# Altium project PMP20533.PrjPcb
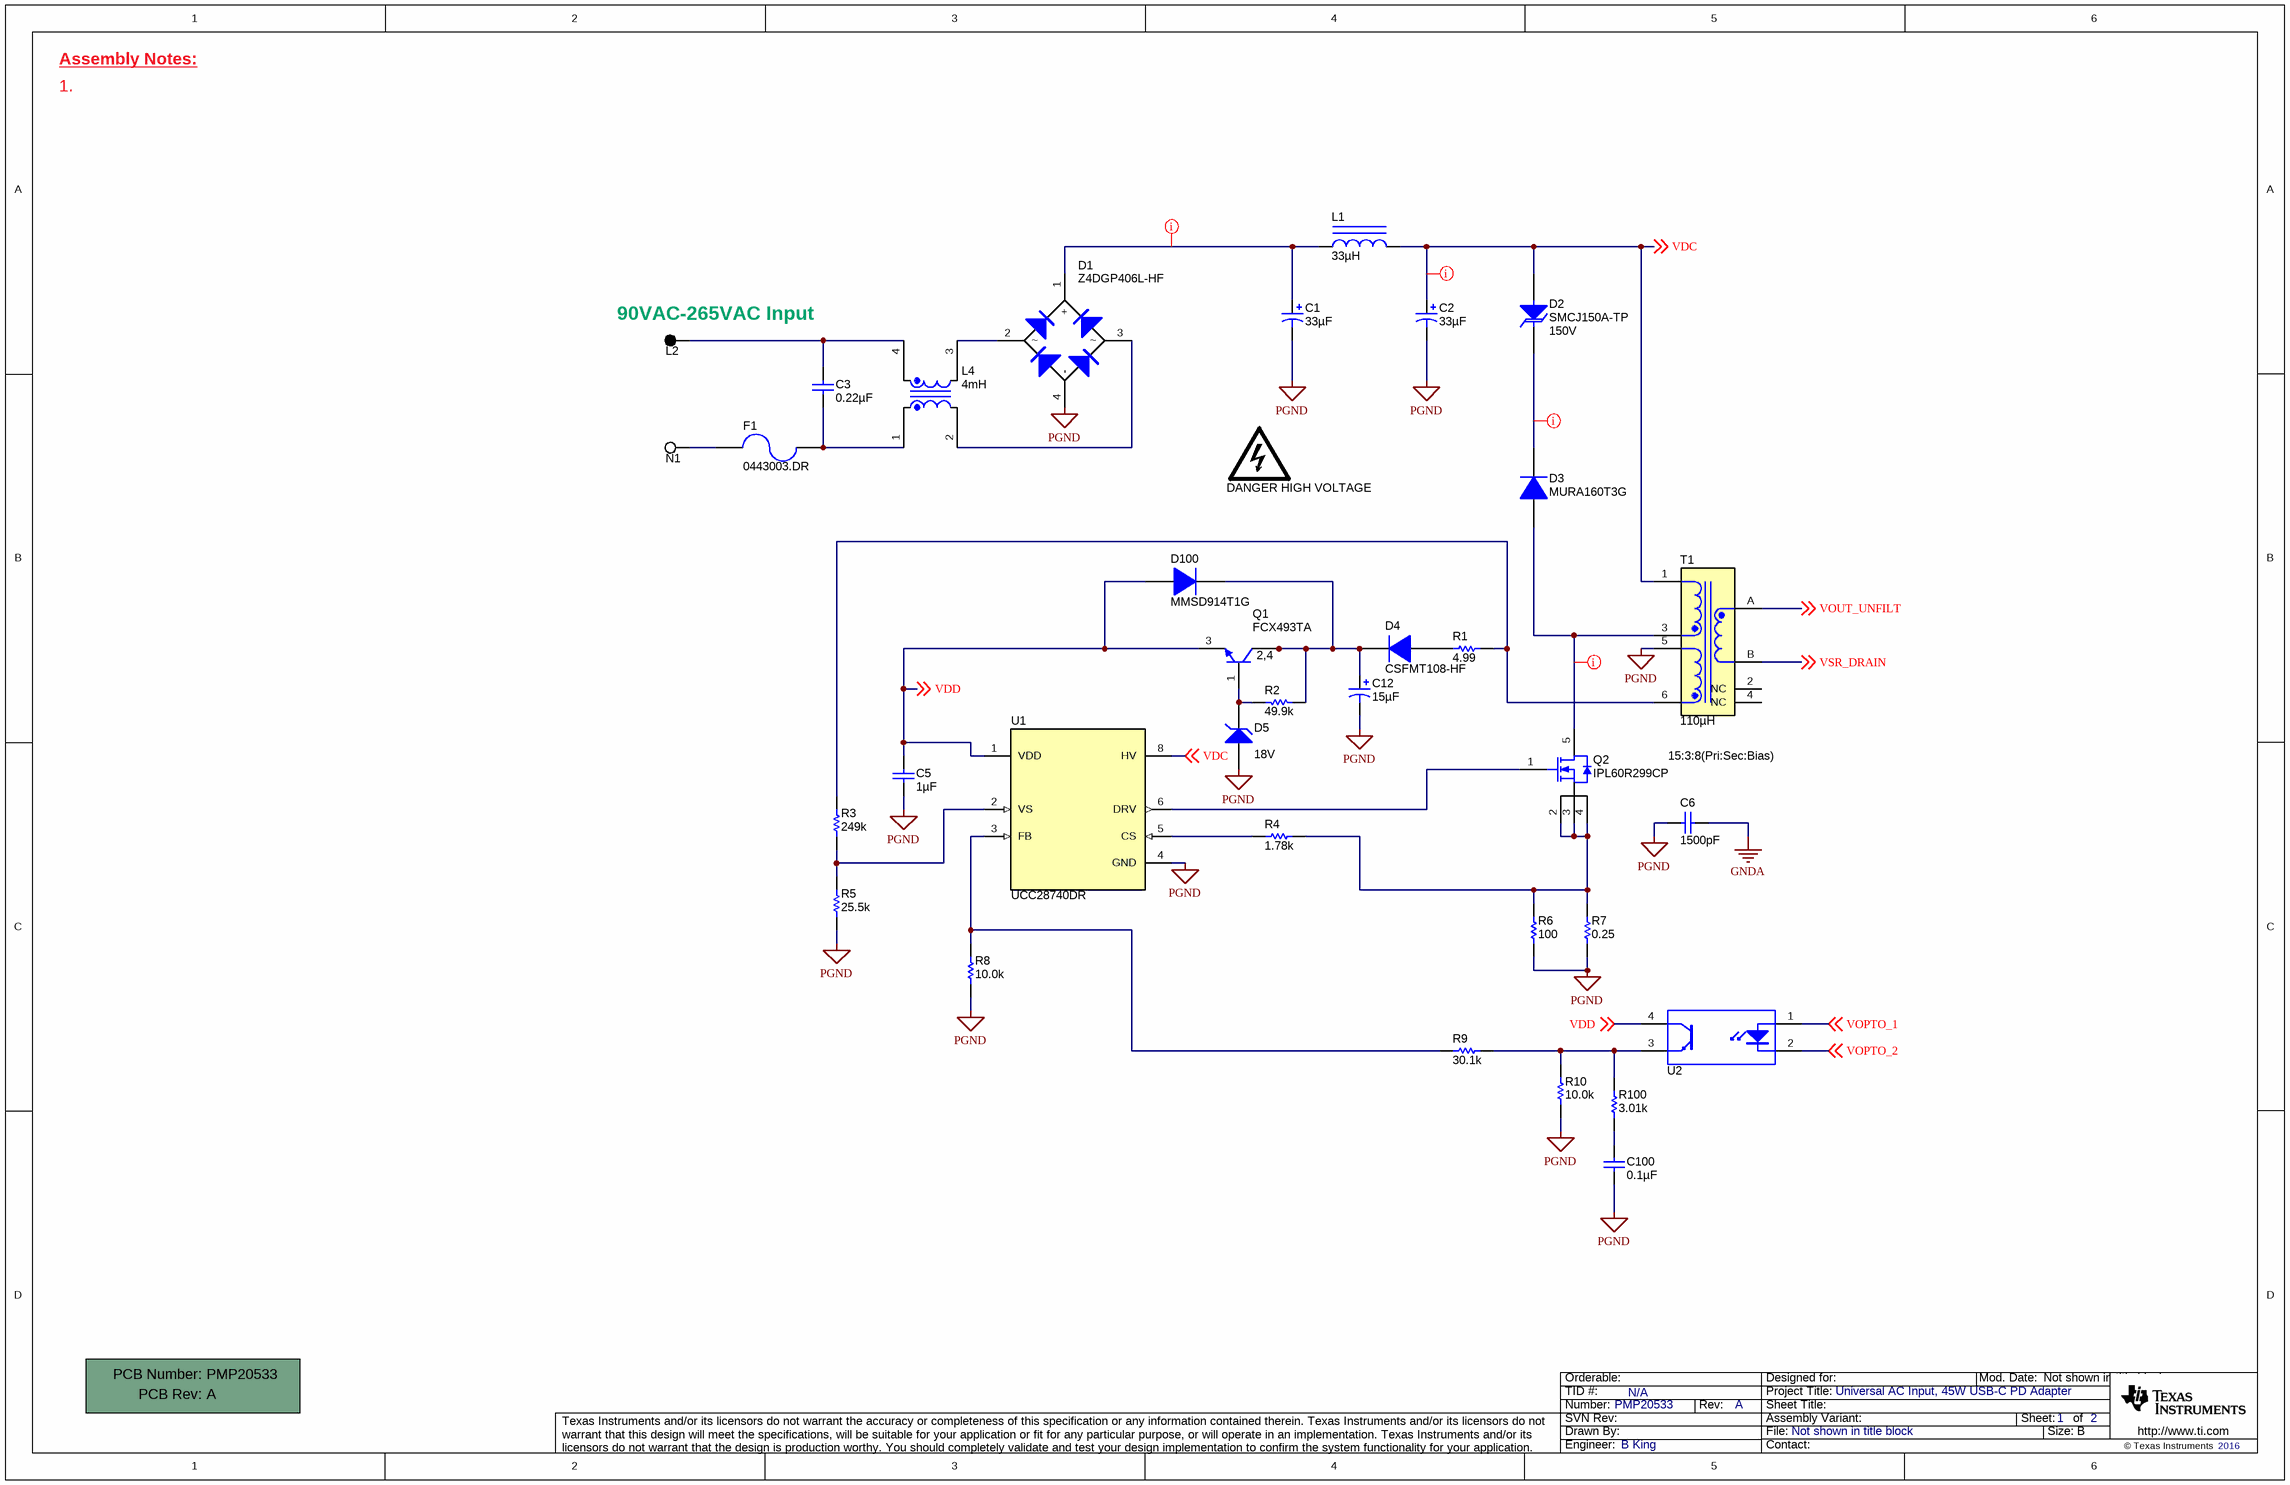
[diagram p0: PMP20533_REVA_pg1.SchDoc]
TID: N/A; SCH_Rev: A; PRJ_Title: Universal AC Input, 45W USB-C PD Adapter; PRJ_Number: PMP20533; PRJ_Engineer: B King; PCB_Rev: A; PCB_Layout: B King; CopyrightYear: 2016
2 sheets, 91 parts. Net scope: global (net labels, ports and power ports of the same name join across sheets).
Board file: PMP20533_REVA_PCB.PcbDoc
Sheets:
  PMP20533_REVA_pg1.SchDoc
  PMP20533_REVA_pg2.SchDoc

## Sheet PMP20533_REVA_pg1.SchDoc
size 431 x 279 mm; Date: Not shown in title block; ApprovedBy: Not shown in title block; CheckedBy: Not shown in title block; Author: Not shown in title block; CompanyName: Not shown in title block; Engineer: Not shown in title block; Organization: Not shown in title block; Address1: Not shown in title block; Address2: Not shown in title block; Address3: Not shown in title block; Address4: Not shown in title block; DocumentNumber: 1; Revision: Use project parameter SCH_Rev; SheetNumber: 1; SheetTotal: 2; PageSetup: Record=PageOptions¦CenterHorizontal=True¦CenterVertical=True¦PrintScale=0.64¦XCorrection=1.00¦YCorrection=1.00¦PrintKind=0¦BorderSize=5000000¦LeftOffset=0¦BottomOffset=0¦Orientation=2¦PaperLength=1000¦PaperWidth=1000¦Scale=100¦PaperSource=15¦PrintQuality=600¦MediaType=1¦DitherType=10¦PrintScaleMode=1¦PaperKind=Letter

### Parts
!PCB1  Printed Circuit Board  (value not drawn)  (mechanical)
C1  ValueDisplayed: 33µF  [KXG_1600x2000]  (hidden comment: EKXG401EC3330ML20S)
C2  ValueDisplayed: 33µF  [KXG_1600x2000]  (hidden comment: EKXG401EC3330ML20S)
C3  ValueDisplayed: 0.22µF  [WCAP-FTX2_1500x700x1250]  (hidden comment: 890324024002)
C5  ValueDisplayed: 1µF  [0402L]  (hidden comment: GRM155R61E105KA12D)
C6  ValueDisplayed: 1500pF  [KY_700x500x1000]  (hidden comment: DE2E3KY152MN3AM02)
C12  ValueDisplayed: 15µF  [HE_630x1100]  (hidden comment: UHE2A150MED)
C100  ValueDisplayed: 0.1µF  [0402L]  (hidden comment: GRM155R71C104KA88D)
D1  Z4DGP406L-HF  [Z4-D]
D2  SMCJ150A-TP  value 150V  [SMC]
D3  MURA160T3G  [SMA]
D4  CSFMT108-HF  [SOD-123H]
D5  value 18V  [SOD-123]  (hidden comment: MMSZ5248B-7-F)
D100  MMSD914T1G  [SOD-123]
F1  0443003.DR  [FUSE_0443]
L1  ValueDisplayed: 33µH  [DR73]  (hidden comment: DR73-330-R)
L2  5001  [Keystone5001]  (value not drawn)
L4  ValueDisplayed: 4mH  [WE-CMB_XS]  (hidden comment: 744821240)
LOGO1  DANGER HIGH VOLTAGE  [IEC_HighVoltage_Small]  (no BOM)
N1  5002  [Keystone5002]  (value not drawn)
Q1  FCX493TA  [SOT-89-3]
Q2  IPL60R299CP  [PG-VSON-4]
R1  ValueDisplayed: 4.99  [0805_HV1]  (hidden comment: CRCW08054R99FKEA)
R2  ValueDisplayed: 49.9k  [1206L]  (hidden comment: CRCW120649K9FKEA)
R3  ValueDisplayed: 249k  [0402L]  (hidden comment: CRCW0402249KFKED)
R4  ValueDisplayed: 1.78k  [0402L]  (hidden comment: CRCW04021K78FKED)
R5  ValueDisplayed: 25.5k  [0402L]  (hidden comment: CRCW040225K5FKED)
R6  ValueDisplayed: 100  [0603L]  (hidden comment: CRCW0603100RFKEA)
R7  ValueDisplayed: 0.25  [2010L]  (hidden comment: CSRN2010FKR250)
R8  ValueDisplayed: 10.0k  [0402L]  (hidden comment: CRCW040210K0FKED)
R9  ValueDisplayed: 30.1k  [0402L]  (hidden comment: CRCW040230K1FKED)
R10  ValueDisplayed: 10.0k  [0402L]  (hidden comment: CRCW040210K0FKED)
R100  ValueDisplayed: 3.01k  [0402L]  (hidden comment: CRCW04023K01FKED)
T1  ValueDisplayed: 110µH  [Renco_RLTI-1178]  (hidden comment: RLTI-1178)
U1  UCC28740DR  [D0007A_L]
U2  LTV-817S  [DIP254P762X350-4]  (value not drawn)

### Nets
GNDA: C6.1
PGND: C1.2(-) C2.2(-) C5.2 C6.2 C12.2(-) C100.2 D1.4(-) D5.2(A) R5.1 R6.1 R7.1 R8.1 R10.1 T1.5 U1.4(GND)
VDC: C2.1(+) D2.2(A) L1.2 T1.1 U1.8(HV) ; off-sheet VDC
VDD: C5.1 D100.2(A) Q1.3(E) U1.1(VDD) U2.4(C) ; off-sheet VDD
VOPTO_1: U2.1(A) ; off-sheet VOPTO_1
VOPTO_2: U2.2(K) ; off-sheet VOPTO_2
VOUT_UNFILT: T1.A ; off-sheet VOUT_UNFILT
VSR_DRAIN: T1.B ; off-sheet VSR_DRAIN
NetC1_1: C1.1(+) D1.1(+) L1.1
NetC3_1: C3.1 L2.1 L4.4
NetC3_2: C3.2 F1.2 L4.1
NetC12_1: C12.1(+) D4.1(K) D100.1(K) Q1.2(C) Q1.4(C) R2.1
NetC100_1: C100.1 R100.1
NetD1_2: D1.2 L4.3
NetD1_3: D1.3 L4.2
NetD2_1: D2.1(K) D3.1(K)
NetD3_2: D3.2(A) Q2.5(D) T1.3
NetD4_2: D4.2(A) R1.1
NetD5_1: D5.1(K) Q1.1(B) R2.2
NetF1_1: F1.1 N1.1
NetQ2_1: Q2.1(G) U1.6(DRV)
NetQ2_2: Q2.2(S) Q2.3(S) Q2.4(S) R4.2 R6.2 R7.2
NetR1_2: R1.2 R3.2 T1.6
NetR3_1: R3.1 R5.2 U1.2(VS)
NetR4_1: R4.1 U1.5(CS)
NetR8_2: R8.2 R9.2 U1.3(FB)
NetR9_1: R9.1 R10.2 R100.2 U2.3(E)

Not connected (* = marked no-connect by the designer): T1 2(NC) 4(NC)

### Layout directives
rule Clearance Constraint [Clearance = 25mil]: NetC1_1, NetD2_1, NetD3_2, VDC

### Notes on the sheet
- Assembly Notes:
- 1.
- (near L2) 90VAC-265VAC Input
- 15:3:8(Pri:Sec:Bias)

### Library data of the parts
!PCB1 = PCB: Manufacturer: Any; PartNumber: PMP20533; SymbolCreator: a0412235
C1 C2 = EKXG401EC3330ML20S: CAP, AL, 33 µF, 400 V, +/- 20%, TH; Manufacturer: Chemi-Con; Polarized: Y; CompType: Capacitor; Value: 33uF; U/M: EA; Cap_F: 0.000033; Tolerance_%: 20; Value1: Unknown; VDC_V: 400; Value2: 400V; IRMS_A: 0.36; TaMin_C: -40; TaMax_C: 105; Cap_Case: 16x20mm; AEC Category: Q200; AEC Qualified: N
C3 = 890324024002: CAP, Film, 0.22 µF, 275 V, +/- 10%, TH; Manufacturer: Wurth Elektronik; Polarized: N; CompType: Capacitor; Value: 0.22uF; U/M: EA; Cap_F: 0.00000022; Tolerance_%: 10; Value1: Unknown; VDC_V: 275; Value2: 275V; TaMin_C: -40; TaMax_C: 105; Cap_Case: 15x7x12.5; SizeAreaWB_mm2: 153; SizeX_mm: 15; SizeY_mm: 7; SizeZ_mm: 13; AEC Category: Q200
C5 = GRM155R61E105KA12D: CAP, CERM, 1 µF, 25 V, +/- 10%, X5R, 0402; Manufacturer: MuRata; Polarized: N; CompType: Capacitor; Value: 1uF; U/M: EA; Cap_F: 0.000001; Tolerance_%: 10; Value1: Unknown; VDC_V: 25; Value2: 25V; TaMin_C: -55; TaMax_C: 85; Cap_Case: 0402
C6 = DE2E3KY152MN3AM02: CAP, CERM, 1500 pF, 250 V, +/- 20%, E, TH, 2- Leads, Body 7x5mm, Pin Spacing 7.5mm; Manufacturer: MuRata; Polarized: N; CompType: Capacitor; Value: 1500pF; U/M: EA; Cap_F: 0.0000000015; Tolerance_%: 20; Value1: Unknown; VDC_V: 250; Value2: 250V; TaMin_C: -25; TaMax_C: 85; Cap_Case: 7x5x10mm; AEC Category: Q200
C12 = UHE2A150MED: CAP, AL, 15 µF, 100 V, +/- 20%, 1.2 ohm, TH; Manufacturer: Nichicon; Polarized: Y; CompType: Capacitor; Value: 15uF; U/M: EA; Cap_F: 0.000015; Tolerance_%: 20; ESR_ohm: 1.2; Value1: 1.2 ohm; VDC_V: 100; Value2: 100V; IRMS_A: 0.126; TaMin_C: -40; TaMax_C: 105; Cap_Case: 6.3x11mm; AEC Category: Q200; AEC Qualified: N
C100 = GRM155R71C104KA88D: CAP, CERM, 0.1 µF, 16 V, +/- 10%, X7R, 0402; Manufacturer: MuRata; Polarized: N; CompType: Capacitor; Value: 0.1uF; U/M: EA; Cap_F: 0.0000001; Tolerance_%: 10; Value1: Unknown; VDC_V: 16; Value2: 16V; TaMin_C: -55; TaMax_C: 125; Cap_Case: 0402
D1 = Z4DGP406L-HF: Diode, P-N-Bridge, 600 V, 4 A, Z4-D; Manufacturer: Comchip Technology; U/M: EA; Vf_V: 0.95; Value: 600V; Value1: 4A; Value2: 0.95V; Io_A: 4; Vr_V: 600; TJmax_C: 175
D2 = SMCJ150A-TP: Diode, TVS, Uni, 150 V, 1500 W, SMC; Manufacturer: Micro Commercial Components; U/M: EA; Power_W: 1500; Vr_V: 150; Value1: 1500W; AEC Category: Q101; AEC Qualified: N
D3 = MURA160T3G: Diode, Ultrafast, 600 V, 1 A, SMA; Manufacturer: ON Semiconductor; U/M: EA; Vf_V: 1.05; Value: 600V; Value1: 1A; Value2: 1.05V; Io_A: 1; Vr_V: 600; TJmax_C: 175; AEC Category: Q101
D4 = CSFMT108-HF: Diode, Superfast Rectifier, 600 V, 1 A, 3.5x1.6mm; Manufacturer: Comchip Technology; U/M: EA; Vf_V: 1.7; Value: 600V; Value1: 1A; Value2: 1.7V; Io_A: 1; Vr_V: 600; TJmax_C: 150
D5 = MMSZ5248B-7-F: Diode, Zener, 18 V, 500 mW, SOD-123; Manufacturer: Diodes Inc.; SymbolCreator: a0412235; U/M: EA; Power_W: 0.5; Vz_V: 18; Value1: 0.5W; RJA_CperW: 350; AEC Category: Q101
D100 = MMSD914T1G: Diode, Switching, 100 V, 0.2 A, SOD-123; Manufacturer: ON Semiconductor; U/M: EA; Value: 100V; Value1: 0.2A; Io_A: 0.2; Vr_V: 100; TJmax_C: 150; SizeAreaWB_mm2: 13.095; SizeArea_mm2: 6.545; SizeX_mm: 3.85; SizeY_mm: 1.7; SizeZ_mm: 1.35; AEC Category: Q101
F1 = 0443003.DR: Fuse, 3 A, 250 V, SMD; Manufacturer: Littelfuse; U/M: EA; OpeningTime_100%_min: 4; OpeningTime_200%_max: 120; VDC_V: 250; Interrupt_AC: 50; Irating_A: 3; Rtyp_Ohm: 0.028; MeltingTyp: 51.44; Vdrop: 0.113; Soldering_Wave_MaxTemp_C: 260; Soldering_Reflow_MaxTemp_C: 217; Soldering_Reflow_MaxTime_s: 90
L1 = DR73-330-R: Inductor, Shielded Drum Core, Ferrite, 33 µH, 1.31 A, 0.166 ohm, SMD; Manufacturer: Coiltronics; Value: 33uH; Ind_H: 33.0E-6; Imax_A: 1.31; Irms: 1.31A @ 40C rise; Isat: 1.35A @ 30% inductance drop; DCR_ohm: 0.166; Value2: 1.31A; AEC Category: Q200
L2 = 5001: Test Point, Miniature, Black, TH; Manufacturer: Keystone; CompType: Test Point Loop; ContactFinish: Silver
L4 = 744821240: Coupled inductor, 4 mH, 1.5 A, 0.14 ohm, TH; Manufacturer: Wurth Elektronik; SymbolCreator: a0412235; Value: 4mH; Ind_H: 4.0E-3; DCR_ohm: 0.14; SizeAreaWB_mm2: 161.5; SizeArea_mm2: 112.5; SizeX_mm: 15; SizeY_mm: 7.5; SizeZ_mm: 20.5
LOGO1 = IEC_HighVoltage: IEC 61010-1 High Voltage Warning; SymbolCreator: a0412235
N1 = 5002: Test Point, Miniature, White, TH; Manufacturer: Keystone; CompType: Test Point Loop; ContactFinish: Silver
Q1 = FCX493TA, Diodes Inc.: Transistor, NPN, 100 V, 1 A, SOT-89; SymbolCreator: a0412235; PNP: 0; NPN: 1; Vceo_V: 100; Vcesat1_V: 0.6; Value: 100 V; Value1: 1 A; HfeMax: 300; TaMin_C: -65; TaMax_C: 150; CompType: BJT; U/M: EA; AEC Category: Q101
Q2 = IPL60R299CP: MOSFET, N-CH, 650 V, 11.1 A, PG-VSON-4; Manufacturer: Infineon Technologies; Alternate Manufacturer: None; SymbolCreator: a0411947; U/M: EA; ChType: N; Value: 650V; VdsMax_V: 650; Value1: ? ohm; Value2: 22 nC; QgTyp_nC: 22; Vgs_V: 20; IdsMax_A: 11.1; AEC Category: Q101
R1 = CRCW08054R99FKEA: RES, 4.99, 1%, 0.125 W, 0805; Manufacturer: Vishay-Dale; CompType: Resistor; Value: 4.99; Value_Code: 4R99; Tolerance_%: 1; Power_W: 0.125; Value2: 0.125W; VDC_V: 150; TempCo: 100 ppm/C; EIA_Code: E96; U/M: EA; AEC Category: Q200
R2 = CRCW120649K9FKEA: RES, 49.9 k, 1%, 0.25 W, 1206; Manufacturer: Vishay-Dale; CompType: Resistor; Value: 49.9k; Res_ohm: 49900; Value_Code: 49k9; Tolerance_%: 1; Power_W: 0.25; Value2: 0.25W; VDC_V: 200; TempCo: 100 ppm/C; EIA_Code: E96; U/M: EA; AEC Category: Q200
R3 = CRCW0402249KFKED: RES, 249 k, 1%, 0.063 W, 0402; Manufacturer: Vishay-Dale; CompType: Resistor; Value: 249k; Res_ohm: 249000; Tolerance_%: 1; Power_W: 0.063; Value2: 0.063W; VDC_V: 50; TempCo: 100 ppm/C; EIA_Code: E96; U/M: EA; AEC Category: Q200
R4 = CRCW04021K78FKED: RES, 1.78 k, 1%, 0.063 W, 0402; Manufacturer: Vishay-Dale; CompType: Resistor; Value: 1.78k; Res_ohm: 1780; Value_Code: 1k78; Tolerance_%: 1; Power_W: 0.063; Value2: 0.063W; VDC_V: 50; TempCo: 100 ppm/C; EIA_Code: E96; U/M: EA
R5 = CRCW040225K5FKED: RES, 25.5 k, 1%, 0.063 W, 0402; Manufacturer: Vishay-Dale; CompType: Resistor; Value: 25.5k; Res_ohm: 25500; Value_Code: 25k5; Tolerance_%: 1; Power_W: 0.063; Value2: 0.063W; VDC_V: 50; TempCo: 100 ppm/C; EIA_Code: E96; U/M: EA; AEC Category: Q200; SizeArea_mm2: 0.5; SizeZ_mm: 0.6
R6 = CRCW0603100RFKEA: RES, 100, 1%, 0.1 W, 0603; Manufacturer: Vishay-Dale; CompType: Resistor; Value: 100; Value_Code: 100R; Tolerance_%: 1; Power_W: 0.1; Value2: 0.1W; VDC_V: 75; TempCo: 100 ppm/C; EIA_Code: E96; U/M: EA; AEC Category: Q200
R7 = CSRN2010FKR250: RES, 0.25, 1%, 1 W, 2010; Manufacturer: Stackpole Electronics Inc; CompType: Resistor; Value: 0.25; Value_Code: R250; Tolerance_%: 1; Value2: 1W; TempCo: 250 ppm/C; U/M: EA; AEC Category: Q200
R8 R10 = CRCW040210K0FKED: RES, 10.0 k, 1%, 0.063 W, 0402; Manufacturer: Vishay-Dale; CompType: Resistor; Value: 10.0k; Res_ohm: 10000; Value_Code: 10k0; Tolerance_%: 1; Power_W: 0.063; Value2: 0.063W; VDC_V: 50; TempCo: 100 ppm/C; EIA_Code: E96; U/M: EA
R9 = CRCW040230K1FKED: RES, 30.1 k, 1%, 0.063 W, 0402; Manufacturer: Vishay-Dale; CompType: Resistor; Value: 30.1k; Res_ohm: 30100; Value_Code: 30k1; Tolerance_%: 1; Power_W: 0.063; Value2: 0.063W; VDC_V: 50; TempCo: 100 ppm/C; EIA_Code: E96; U/M: EA
R100 = CRCW04023K01FKED: RES, 3.01 k, 1%, 0.063 W, 0402; Manufacturer: Vishay-Dale; CompType: Resistor; Value: 3.01k; Res_ohm: 3010; Value_Code: 3k01; Tolerance_%: 1; Power_W: 0.063; Value2: 0.063W; VDC_V: 50; TempCo: 100 ppm/C; EIA_Code: E96; U/M: EA; SizeArea_mm2: 0.5; SizeZ_mm: 0.6; AEC Category: Q200
T1 = RLTI-1178: Transformer, 110 uH, TH; Manufacturer: Renco Electronics; SymbolCreator: Altium; Value: 110uH; Lp: 110; DCR_ohm: 0.04; LeakageL: 3; Rs1: 0.003
U1 = UCC28740DR: Constant-Voltage, Constant-Current Flyback Controller Using Opto-Coupler Feedback, D0007A; Manufacturer: Texas Instruments; SymbolCreator: a0412235; CompType: IC; U/M: EA
U2 = LTV-817S: Optocoupler, 5 kV, 50-600% CTR, SMT; Manufacturer: Lite-On; CTR (Min): 50%; CTR (Max): 600%; Voltage_Isolation_Vrms: 5000V

## Sheet PMP20533_REVA_pg2.SchDoc
size 431 x 279 mm; Date: Not shown in title block; ApprovedBy: Not shown in title block; CheckedBy: Not shown in title block; Author: Not shown in title block; CompanyName: Not shown in title block; Engineer: Not shown in title block; Organization: Not shown in title block; Address1: Not shown in title block; Address2: Not shown in title block; Address3: Not shown in title block; Address4: Not shown in title block; DocumentNumber: 2; Revision: Use project parameter SCH_Rev; SheetNumber: 2; SheetTotal: 2; PageSetup: Record=PageOptions¦CenterHorizontal=True¦CenterVertical=True¦PrintScale=1.00¦XCorrection=1.00¦YCorrection=1.00¦PrintKind=0¦BorderSize=5000000¦LeftOffset=0¦BottomOffset=0¦Orientation=2¦PaperLength=1000¦PaperWidth=1000¦Scale=100¦PaperSource=15¦PrintQuality=600¦MediaType=1¦DitherType=10¦PaperKind=Letter¦PrintScaleMode=1
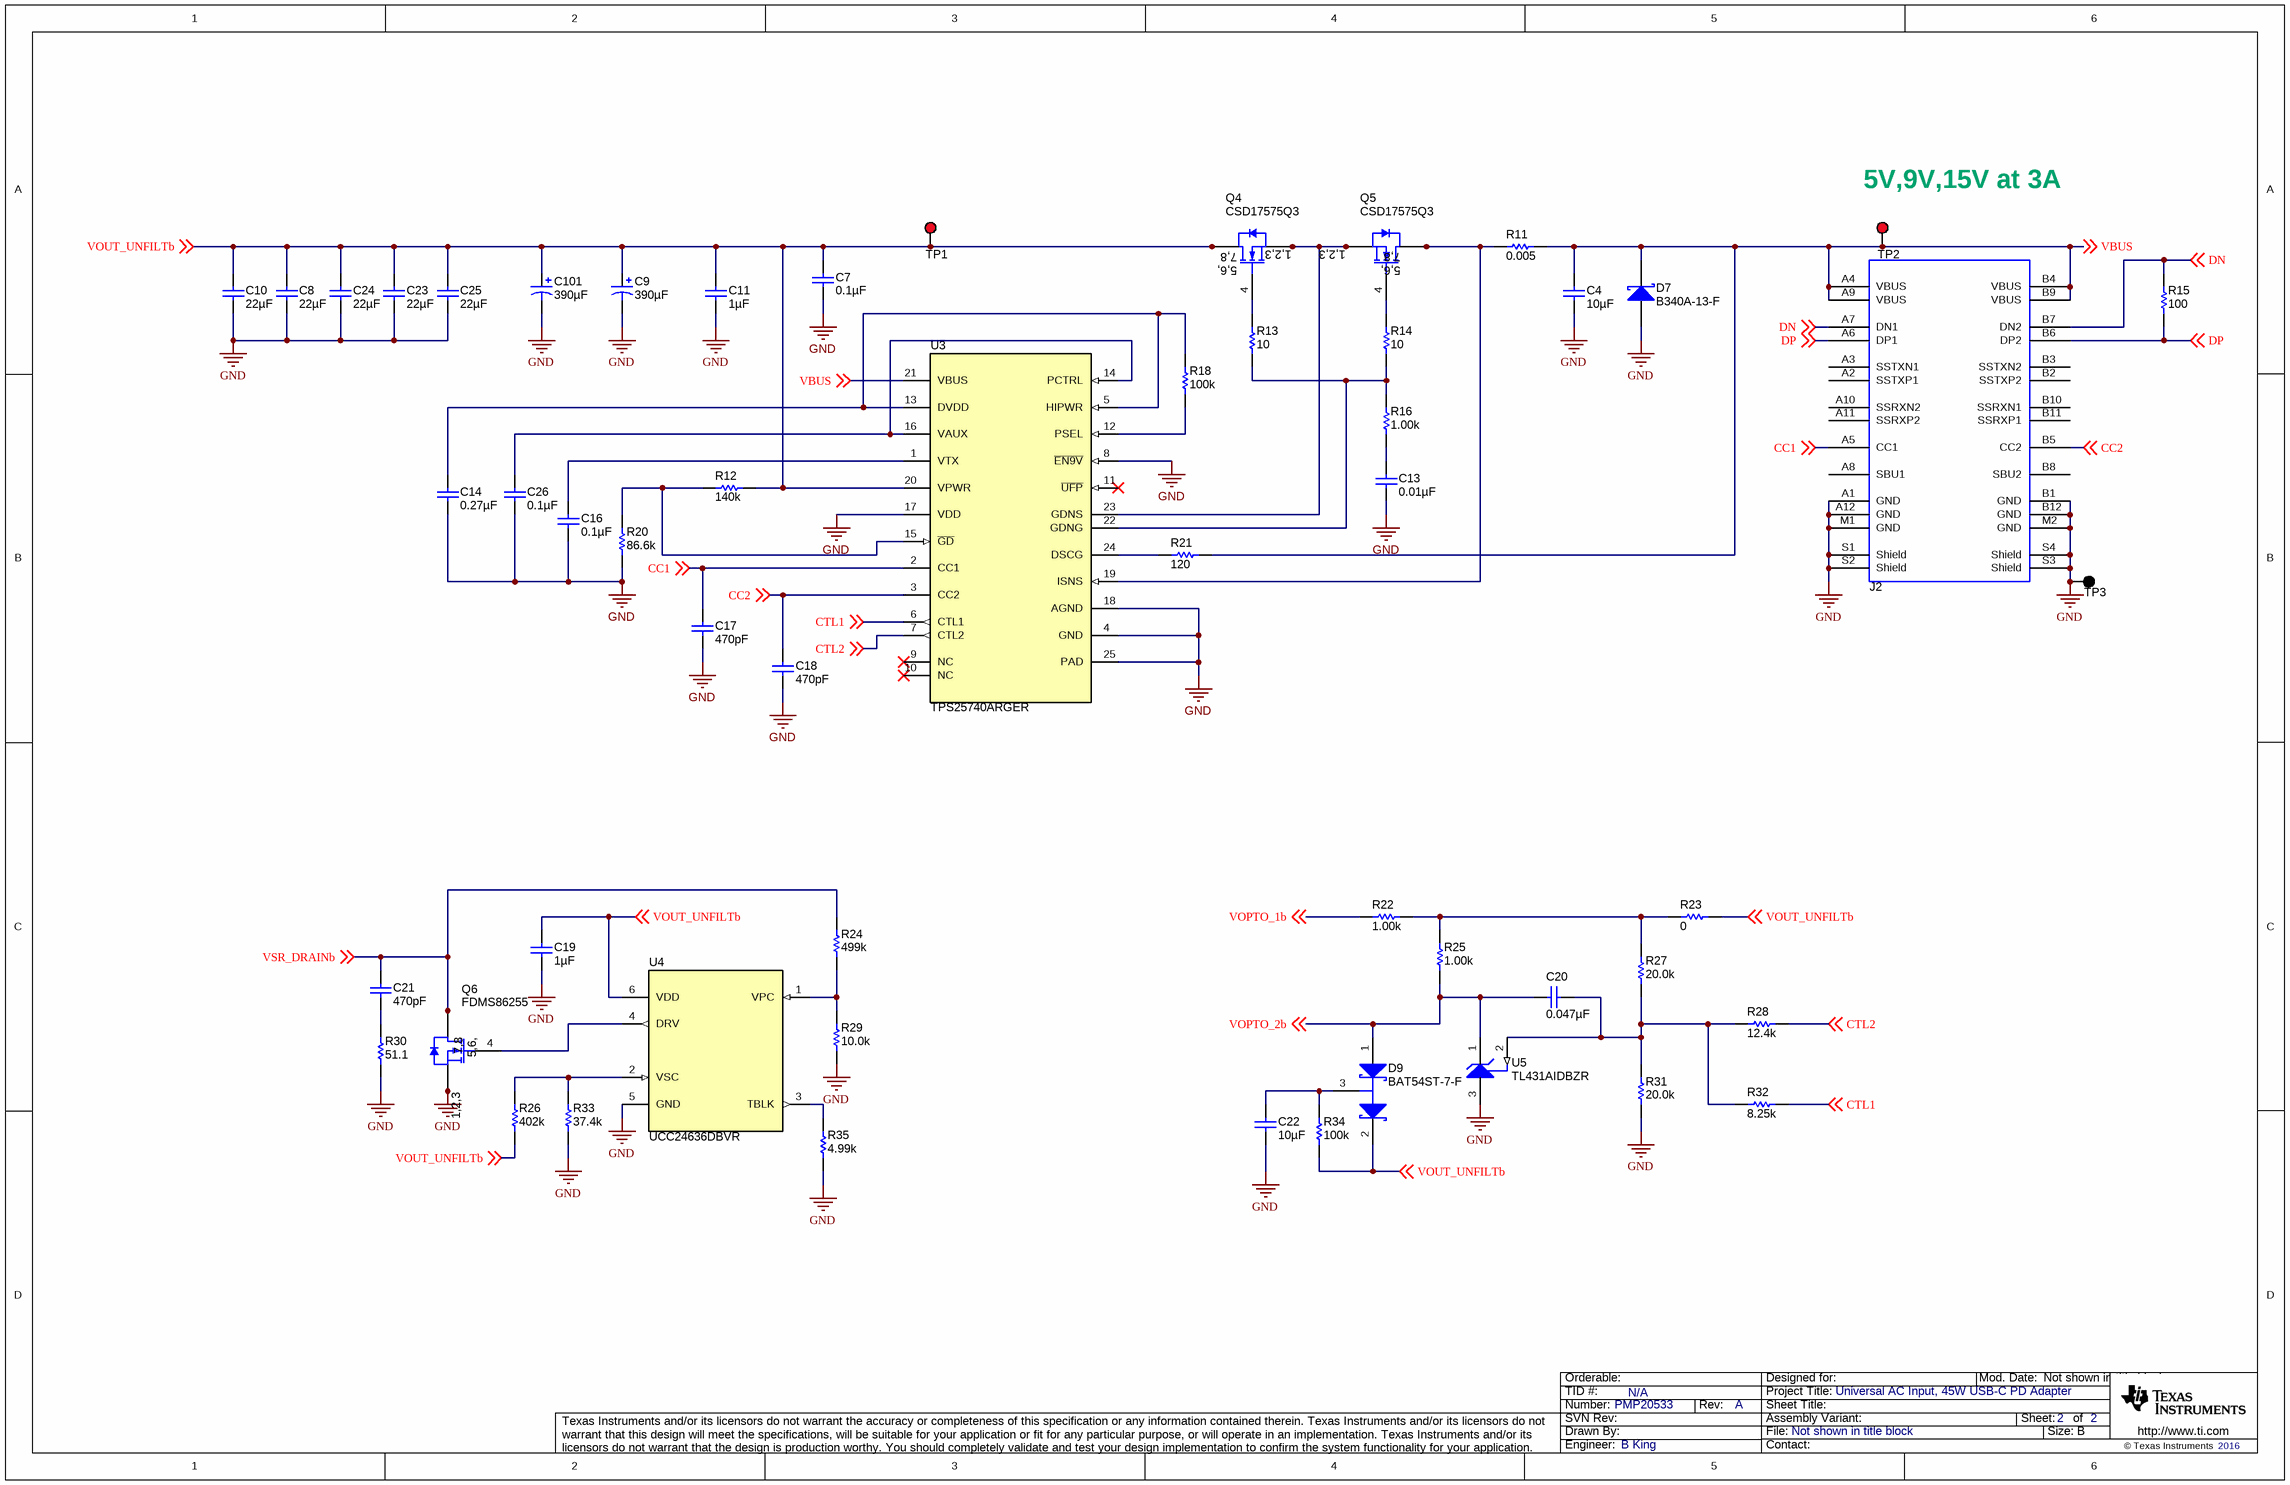
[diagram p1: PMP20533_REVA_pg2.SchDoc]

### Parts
C4  ValueDisplayed: 10µF  [0805_HV1]  (hidden comment: GRM21BR6YA106KE43L)
C7  ValueDisplayed: 0.1µF  [0402L]  (hidden comment: GRM155R71C104KA88D)
C8  ValueDisplayed: 22µF  [1206_180]  (hidden comment: GRT31CR61E226KE01L)
C9  ValueDisplayed: 390µF  [SEPF_E12_HorizontalUP]  (hidden comment: 20SEPF390M)
C10  ValueDisplayed: 22µF  [1206_180]  (hidden comment: GRT31CR61E226KE01L)
C11  ValueDisplayed: 1µF  [0402L]  (hidden comment: GRM155R61E105KA12D)
C13  ValueDisplayed: 0.01µF  [0402L]  (hidden comment: GRM155R71H103KA88D)
C14  ValueDisplayed: 0.27µF  [0402L]  (hidden comment: GRM155R60J274KE01D)
C16  ValueDisplayed: 0.1µF  [0402L]  (hidden comment: GRM155R71C104KA88D)
C17  ValueDisplayed: 470pF  [0402L]  (hidden comment: GRM155R71H471KA01D)
C18  ValueDisplayed: 470pF  [0402L]  (hidden comment: GRM155R71H471KA01D)
C19  ValueDisplayed: 1µF  [0402L]  (hidden comment: GRM155R61E105KA12D)
C20  ValueDisplayed: 0.047µF  [0402L]  (hidden comment: GRM155R71E473KA88D)
C21  ValueDisplayed: 470pF  [0603L]  (hidden comment: GRM188R72E471KW07D)
C22  ValueDisplayed: 10µF  [0805_HV1]  (hidden comment: GRM21BR6YA106KE43L)
C23  ValueDisplayed: 22µF  [1206_180]  (hidden comment: GRT31CR61E226KE01L)
C24  ValueDisplayed: 22µF  [1206_180]  (hidden comment: GRT31CR61E226KE01L)
C25  ValueDisplayed: 22µF  [1206_180]  (hidden comment: GRT31CR61E226KE01L)
C26  ValueDisplayed: 0.1µF  [0402L]  (hidden comment: GRM155R71C104KA88D)
C101  ValueDisplayed: 390µF  [SEPF_E12_HorizontalUP]  (hidden comment: 20SEPF390M)
D7  B340A-13-F  [SMA]
D9  BAT54ST-7-F  [SOT-523]
J2  632 723 300 011  [Wurth_632_723_300_011]  (value not drawn)
Q4  CSD17575Q3  [DQG0008A]
Q5  CSD17575Q3  [DQG0008A]
Q6  FDMS86255  [TRANS_NexFET_Q5B]
R11  ValueDisplayed: 0.005  [1206L]  (hidden comment: WSL12065L000FEA)
R12  ValueDisplayed: 140k  [0402L]  (hidden comment: CRCW0402140KFKED)
R13  ValueDisplayed: 10  [0402L]  (hidden comment: CRCW040210R0JNED)
R14  ValueDisplayed: 10  [0402L]  (hidden comment: CRCW040210R0JNED)
R15  ValueDisplayed: 100  [0402L]  (hidden comment: CRCW0402100RJNED)
R16  ValueDisplayed: 1.00k  [0402L]  (hidden comment: CRCW04021K00FKED)
R18  ValueDisplayed: 100k  [0402L]  (hidden comment: CRCW0402100KFKED)
R20  ValueDisplayed: 86.6k  [0402L]  (hidden comment: CRCW040286K6FKED)
R21  ValueDisplayed: 120  [0805_HV1]  (hidden comment: RG2012P-121-B-T5)
R22  ValueDisplayed: 1.00k  [0603L]  (hidden comment: CRCW06031K00FKEA)
R23  ValueDisplayed: 0  [0402L]  (hidden comment: CRCW04020000Z0ED)
R24  ValueDisplayed: 499k  [0402L]  (hidden comment: CRCW0402499KFKED)
R25  ValueDisplayed: 1.00k  [0603L]  (hidden comment: CRCW06031K00FKEA)
R26  ValueDisplayed: 402k  [0402L]  (hidden comment: CRCW0402402KFKED)
R27  ValueDisplayed: 20.0k  [0402L]  (hidden comment: CRCW040220K0FKED)
R28  ValueDisplayed: 12.4k  [0402L]  (hidden comment: CRCW040212K4FKED)
R29  ValueDisplayed: 10.0k  [0402L]  (hidden comment: CRCW040210K0FKED)
R30  ValueDisplayed: 51.1  [1206L]  (hidden comment: ERJ-8ENF51R1V)
R31  ValueDisplayed: 20.0k  [0402L]  (hidden comment: CRCW040220K0FKED)
R32  ValueDisplayed: 8.25k  [0402L]  (hidden comment: CRCW04028K25FKED)
R33  ValueDisplayed: 37.4k  [0402L]  (hidden comment: CRCW040237K4FKED)
R34  ValueDisplayed: 100k  [0402L]  (hidden comment: CRCW0402100KFKED)
R35  ValueDisplayed: 4.99k  [0402L]  (hidden comment: CRCW04024K99FKED)
TP1  VBUS  [Keystone5000]  (value not drawn)
TP2  VBUS  [Keystone5000]  (value not drawn)
TP3  5001  [Keystone5001]  (value not drawn)
U3  TPS25740ARGER  [RGE0024F]
U4  UCC24636DBVR  [DBV0006A_N]
U5  TL431AIDBZR  [DBZ0003A_L]

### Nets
GND: C4.2 C7.2 C8.2 C9.2(-) C10.2 C11.2 C13.2 C14.2 C16.2 C17.2 C18.2 C19.2 C22.2 C23.2 C24.2 C25.2 C26.2 C101.2(-) D7.2(A) J2.A1(GND) J2.A12(GND) J2.B1(GND) J2.B12(GND) J2.M1(GND) J2.M2(GND) J2.S1(Shield) J2.S2(Shield) J2.S3(Shield) J2.S4(Shield) Q6.1(S) Q6.2(S) Q6.3(S) R20.1 R29.1 R30.1 R31.1 R33.1 R35.1 TP3.1 U3.4(GND) U3.8(~{EN9V}) U3.17(VDD) U3.18(AGND) U3.25(PAD) U4.5(GND) U5.3(ANODE)
CC1: C17.1 J2.A5(CC1) U3.2(CC1) ; off-sheet CC1
CC2: C18.1 J2.B5(CC2) U3.3(CC2) ; off-sheet CC2
CTL1: R32.1 U3.6(CTL1) ; off-sheet CTL1
CTL2: R28.1 U3.7(CTL2) ; off-sheet CTL2
DN: J2.A7(DN1) J2.B7(DN2) R15.1 ; off-sheet DN
DP: J2.A6(DP1) J2.B6(DP2) R15.2 ; off-sheet DP
VBUS: C4.1 D7.1(K) J2.A4(VBUS) J2.A9(VBUS) J2.B4(VBUS) J2.B9(VBUS) R11.1 R21.2 TP2.1 U3.21(VBUS) ; off-sheet VBUS
VOPTO_1b: R22.1 ; off-sheet VOPTO_1b
VOPTO_2b: C20.1 D9.1(A) R25.2 U5.1(CATHODE) ; off-sheet VOPTO_2b
VOUT_UNFILTb: C7.1 C8.1 C9.1(+) C10.1 C11.1 C19.1 C23.1 C24.1 C25.1 C101.1(+) D9.2(K) Q4.5(D) Q4.6(D) Q4.7(D) Q4.8(D) Q4.9(D) R12.1 R23.2 R26.2 R34.1 TP1.1 U3.20(VPWR) U4.6(VDD) ; off-sheet VOUT_UNFILTb
VSR_DRAINb: C21.2 Q6.5(D) Q6.6(D) Q6.7(D) Q6.8(D) R24.2 ; off-sheet VSR_DRAINb
NetC13_1: C13.1 R16.2
NetC14_1: C14.1 R18.1 U3.5(HIPWR) U3.13(DVDD)
NetC16_1: C16.1 U3.1(VTX)
NetC20_2: C20.2 R27.1 R28.2 R31.2 R32.2 U5.2(REF)
NetC21_1: C21.1 R30.2
NetC22_1: C22.1 D9.3(C) R34.2
NetC26_1: C26.1 U3.14(PCTRL) U3.16(VAUX)
NetQ4_1: Q4.1(S) Q4.2(S) Q4.3(S) Q5.1(S) Q5.2(S) Q5.3(S) U3.23(GDNS)
NetQ4_4: Q4.4(G) R13.1
NetQ5_4: Q5.4(G) R14.1
NetQ5_5: Q5.5(D) Q5.6(D) Q5.7(D) Q5.8(D) Q5.9(D) R11.2 U3.19(ISNS)
NetQ6_4: Q6.4(G) U4.4(DRV)
NetR12_2: R12.2 R20.2 U3.15(~{GD})
NetR13_2: R13.2 R14.2 R16.1 U3.22(GDNG)
NetR18_2: R18.2 U3.12(PSEL)
NetR21_1: R21.1 U3.24(DSCG)
NetR22_2: R22.2 R23.1 R25.1 R27.2
NetR24_1: R24.1 R29.2 U4.1(VPC)
NetR26_1: R26.1 R33.2 U4.2(VSC)
NetR35_2: R35.2 U4.3(TBLK)

Not connected (* = marked no-connect by the designer): J2 A2(SSTXP1) A3(SSTXN1) A8(SBU1) A10(SSRXN2) A11(SSRXP2) B2(SSTXP2) B3(SSTXN2) B8(SBU2) B10(SSRXN1) B11(SSRXP1); U3 9(NC)* 10(NC)* 11(~{UFP})*

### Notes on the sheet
- (near TP2) 5V,9V,15V at 3A

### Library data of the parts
C4 C22 = GRM21BR6YA106KE43L: CAP, CERM, 10 µF, 35 V, +/- 10%, X5R, 0805; Manufacturer: MuRata; Polarized: N; CompType: Capacitor; Value: 10uF; U/M: EA; Cap_F: 0.00001; Tolerance_%: 10; Value1: Unknown; VDC_V: 35; Value2: 35V; TaMin_C: -55; TaMax_C: 85; Cap_Case: 0805; AEC Category: Q200
C7 C16 C26 = GRM155R71C104KA88D: as C100 on sheet PMP20533_REVA_pg1
C8 C10 C23-C25 = GRT31CR61E226KE01L: CAP, CERM, 22 µF, 25 V, +/- 10%, X5R, AEC-Q200 Grade 3, 1206; Manufacturer: MuRata; Polarized: N; CompType: Capacitor; Value: 22uF; U/M: EA; Cap_F: 0.000022; Tolerance_%: 10; Value1: Unknown; VDC_V: 25; Value2: 25V; TaMin_C: -55; TaMax_C: 85; Cap_Case: 1206; AEC Category: Q200; AEC Qualified: Y; AEC Grade: 3
C9 C101 = 20SEPF390M: CAP, Aluminum Polymer, 390 µF, 20 V, +20/-0%, 0.014 ohm, TH; Manufacturer: Panasonic; Polarized: Y; CompType: Capacitor; Value: 390uF; U/M: EA; Cap_F: 0.00039; Tolerance_%: 20; Value2: 20V; ESR_ohm: 0.014; IRMS_A: 4.95; TaMin_C: -55; TaMax_C: 105; Cap_Case: E12; AEC Category: Q200; AEC Qualified: N
C11 C19 = GRM155R61E105KA12D: as C5 on sheet PMP20533_REVA_pg1
C13 = GRM155R71H103KA88D: CAP, CERM, 0.01 µF, 50 V, +/- 10%, X7R, 0402; Manufacturer: MuRata; Polarized: N; CompType: Capacitor; Value: 0.01uF; U/M: EA; Cap_F: 0.00000001; Tolerance_%: 10; Value1: Unknown; VDC_V: 50; Value2: 50V; TaMin_C: -55; TaMax_C: 125; Cap_Case: 0402
C14 = GRM155R60J274KE01D: CAP, CERM, 0.27 µF, 6.3 V, +/- 10%, X5R, 0402; Manufacturer: MuRata; Polarized: N; CompType: Capacitor; Value: 0.27uF; U/M: EA; Cap_F: 0.00000027; Tolerance_%: 10; Value1: Unknown; VDC_V: 6.3; Value2: 6.3V; TaMin_C: -55; TaMax_C: 85; Cap_Case: 0402
C17 C18 = GRM155R71H471KA01D: CAP, CERM, 470 pF, 50 V, +/- 10%, X7R, 0402; Manufacturer: MuRata; Polarized: N; CompType: Capacitor; Value: 470pF; U/M: EA; Cap_F: 0.00000000047; Tolerance_%: 10; Value1: Unknown; VDC_V: 50; Value2: 50V; TaMin_C: -55; TaMax_C: 125; Cap_Case: 0402
C20 = GRM155R71E473KA88D: CAP, CERM, 0.047 µF, 25 V, +/- 10%, X7R, 0402; Manufacturer: MuRata; Polarized: N; CompType: Capacitor; Value: 0.047uF; U/M: EA; Cap_F: 0.000000047; Tolerance_%: 10; Value1: Unknown; VDC_V: 25; Value2: 25V; TaMin_C: -55; TaMax_C: 125; Cap_Case: 0402; SizeArea_mm2: 0.5; SizeAreaWB_mm2: 3; SizeX_mm: 1; SizeZ_mm: 0.6; AEC Category: Q200
C21 = GRM188R72E471KW07D: CAP, CERM, 470 pF, 250 V, +/- 10%, X7R, 0603; Manufacturer: MuRata; Polarized: N; CompType: Capacitor; Value: 470pF; U/M: EA; Cap_F: 0.00000000047; Tolerance_%: 10; Value1: Unknown; VDC_V: 250; Value2: 250V; TaMin_C: -55; TaMax_C: 125; Cap_Case: 0603; AEC Category: Q200
D7 = B340A-13-F: Diode, Schottky, 40 V, 3 A, SMA; Manufacturer: Diodes Inc.; U/M: EA; Vf_V: 0.5; Value: 40V; Value1: 3A; Value2: 0.5V; Io_A: 3; Vr_V: 40; TJmax_C: 125; RJC_CperW: 25
D9 = BAT54ST-7-F: Diode, Schottky, 30 V, 0.2 A, SOT-523; Manufacturer: Diodes Inc.; U/M: EA; Vf_V: 1; Value: 30V; Value1: 0.2A; Value2: 1V; Io_A: 0.2; Vr_V: 30; TJmax_C: 125
J2 = 632 723 300 011: Connector, Receptacle, USB Type C, R/A; Manufacturer: Wurth Elektronik; SymbolCreator: a0412235; Gender: Female; ContactFinish: Gold; Current_A: 3; Voltage_V: 5; Cert_UL: Y
Q4 Q5 = CSD17575Q3: MOSFET, N-CH, 30 V, 60 A, DQG0008A; Manufacturer: Texas Instruments; Alternate Manufacturer: None; U/M: EA; ChType: N; Value: 30V; VdsMax_V: 30; Value1: 0.0032 ohm; Rdson45_ohm: 0.0032; Value2: 23 nC; QgTyp_nC: 23; Vgs_V: 20; IdsMax_A: 60; AEC Category: Q101
Q6 = FDMS86255: MOSFET, N-CH, 150 V, 10 A, SON 5x6mm; Manufacturer: Fairchild Semiconductor; Alternate Manufacturer: None; U/M: EA; ChType: N; Value: 150V; VdsMax_V: 150; Value1: ? ohm; Value2: 45 nC; QgTyp_nC: 45; Vgs_V: 20; IdsMax_A: 10; AEC Category: Q101
R11 = WSL12065L000FEA: RES, 0.005, 1%, 0.25 W, 1206; Manufacturer: Vishay-Dale; CompType: Resistor; Value: 0.005; Value_Code: 5L000; Tolerance_%: 1; Power_W: 0.25; Value2: 0.25W; TempCo: 110 ppm/C; EIA_Code: E96; U/M: EA; SizeArea_mm2: 5.12; SizeX_mm: 3.2; SizeY_mm: 1.6; SizeZ_mm: 1.35; AEC Category: Q200; AEC Qualified: N
R12 = CRCW0402140KFKED: RES, 140 k, 1%, 0.063 W, 0402; Manufacturer: Vishay-Dale; CompType: Resistor; Value: 140k; Res_ohm: 140000; Tolerance_%: 1; Power_W: 0.063; Value2: 0.063W; VDC_V: 50; TempCo: 100 ppm/C; EIA_Code: E96; U/M: EA; AEC Category: Q200
R13 R14 = CRCW040210R0JNED: RES, 10, 5%, 0.063 W, 0402; Manufacturer: Vishay-Dale; CompType: Resistor; Value: 10; Value_Code: 10R0; Tolerance_%: 5; Power_W: 0.063; Value2: 0.063W; VDC_V: 50; TempCo: 200 ppm/C; EIA_Code: E24; U/M: EA; AEC Category: Q200
R15 = CRCW0402100RJNED: RES, 100, 5%, 0.063 W, 0402; Manufacturer: Vishay-Dale; CompType: Resistor; Value: 100; Value_Code: 100R; Tolerance_%: 5; Power_W: 0.063; Value2: 0.063W; VDC_V: 50; TempCo: 200 ppm/C; EIA_Code: E24; U/M: EA; AEC Category: Q200
R16 = CRCW04021K00FKED: RES, 1.00 k, 1%, 0.063 W, 0402; Manufacturer: Vishay-Dale; CompType: Resistor; Value: 1.00k; Res_ohm: 1000; Value_Code: 1k00; Tolerance_%: 1; Power_W: 0.063; Value2: 0.063W; VDC_V: 50; TempCo: 100 ppm/C; EIA_Code: E96; U/M: EA; AEC Category: Q200
R18 = CRCW0402100KFKED: RES, 100 k, 1%, 0.063 W, 0402; Manufacturer: Vishay-Dale; CompType: Resistor; Value: 100k; Res_ohm: 100000; Tolerance_%: 1; Power_W: 0.063; Value2: 0.063W; VDC_V: 50; TempCo: 100 ppm/C; EIA_Code: E96; U/M: EA; AEC Category: Q200
R20 = CRCW040286K6FKED: RES, 86.6 k, 1%, 0.063 W, 0402; Manufacturer: Vishay-Dale; CompType: Resistor; Value: 86.6k; Res_ohm: 86600; Value_Code: 86k6; Tolerance_%: 1; Power_W: 0.063; Value2: 0.063W; VDC_V: 50; TempCo: 100 ppm/C; EIA_Code: E96; U/M: EA; AEC Category: Q200
R21 = RG2012P-121-B-T5: RES, 120, 0.1%, 0.125 W, 0805; Manufacturer: Susumu Co Ltd; CompType: Resistor; Value: 120; Value_Code: 120R; Tolerance_%: 0.1; Power_W: 0.125; Value2: 0.125W; VDC_V: 100; TempCo: 25 ppm/C; EIA_Code: E192; U/M: EA
R22 R25 = CRCW06031K00FKEA: RES, 1.00 k, 1%, 0.1 W, 0603; Manufacturer: Vishay-Dale; CompType: Resistor; Value: 1.00k; Res_ohm: 1000; Value_Code: 1k00; Tolerance_%: 1; Power_W: 0.1; Value2: 0.1W; VDC_V: 75; TempCo: 100 ppm/C; EIA_Code: E96; U/M: EA; AEC Category: Q200
R23 = CRCW04020000Z0ED: RES, 0, 5%, 0.063 W, 0402; Manufacturer: Vishay-Dale; CompType: Resistor; Value: 0; Value_Code: 0000; Tolerance_%: 5; Power_W: 0.063; Value2: 0.063W; VDC_V: 50; TempCo: 200 ppm/C; EIA_Code: E24; U/M: EA
R24 = CRCW0402499KFKED: RES, 499 k, 1%, 0.063 W, 0402; Manufacturer: Vishay-Dale; CompType: Resistor; Value: 499k; Res_ohm: 499000; Tolerance_%: 1; Power_W: 0.063; Value2: 0.063W; VDC_V: 50; TempCo: 100 ppm/C; EIA_Code: E96; U/M: EA; AEC Category: Q200; SizeArea_mm2: 0.5; SizeZ_mm: 0.6
R26 = CRCW0402402KFKED: RES, 402 k, 1%, 0.063 W, 0402; Manufacturer: Vishay-Dale; CompType: Resistor; Value: 402k; Res_ohm: 402000; Tolerance_%: 1; Power_W: 0.063; Value2: 0.063W; VDC_V: 50; TempCo: 100 ppm/C; EIA_Code: E96; U/M: EA; AEC Category: Q200; SizeArea_mm2: 0.5; SizeZ_mm: 0.6
R27 R31 = CRCW040220K0FKED: RES, 20.0 k, 1%, 0.063 W, 0402; Manufacturer: Vishay-Dale; CompType: Resistor; Value: 20.0k; Res_ohm: 20000; Value_Code: 20k0; Tolerance_%: 1; Power_W: 0.063; Value2: 0.063W; VDC_V: 50; TempCo: 100 ppm/C; EIA_Code: E96; U/M: EA; AEC Category: Q200
R28 = CRCW040212K4FKED: RES, 12.4 k, 1%, 0.063 W, 0402; Manufacturer: Vishay-Dale; CompType: Resistor; Value: 12.4k; Res_ohm: 12400; Value_Code: 12k4; Tolerance_%: 1; Power_W: 0.063; Value2: 0.063W; VDC_V: 50; TempCo: 100 ppm/C; EIA_Code: E96; U/M: EA; AEC Category: Q200
R29 = CRCW040210K0FKED: as R8 on sheet PMP20533_REVA_pg1
R30 = ERJ-8ENF51R1V: RES, 51.1, 1%, 0.25 W, 1206; Manufacturer: Panasonic; CompType: Resistor; Value: 51.1; Value_Code: 51R1; Tolerance_%: 1; Power_W: 0.25; Value2: 0.25W; VDC_V: 200; TempCo: 100 ppm/C; EIA_Code: E96; U/M: EA; AEC Category: Q200
R32 = CRCW04028K25FKED: RES, 8.25 k, 1%, 0.063 W, 0402; Manufacturer: Vishay-Dale; CompType: Resistor; Value: 8.25k; Res_ohm: 8250; Value_Code: 8k25; Tolerance_%: 1; Power_W: 0.063; Value2: 0.063W; VDC_V: 50; TempCo: 100 ppm/C; EIA_Code: E96; U/M: EA; AEC Category: Q200
R33 = CRCW040237K4FKED: RES, 37.4 k, 1%, 0.063 W, 0402; Manufacturer: Vishay-Dale; CompType: Resistor; Value: 37.4k; Res_ohm: 37400; Value_Code: 37k4; Tolerance_%: 1; Power_W: 0.063; Value2: 0.063W; VDC_V: 50; TempCo: 100 ppm/C; EIA_Code: E96; U/M: EA
R34 = CRCW0402100KFKED: RES, 100 k, 1%, 0.063 W, 0402; Manufacturer: Vishay-Dale; CompType: Resistor; Value: 100k; Res_ohm: 100000; Tolerance_%: 1; Power_W: 0.063; Value2: 0.063W; VDC_V: 50; TempCo: 100 ppm/C; EIA_Code: E96; U/M: EA
R35 = CRCW04024K99FKED: RES, 4.99 k, 1%, 0.063 W, 0402; Manufacturer: Vishay-Dale; CompType: Resistor; Value: 4.99k; Res_ohm: 4990; Value_Code: 4k99; Tolerance_%: 1; Power_W: 0.063; Value2: 0.063W; VDC_V: 50; TempCo: 100 ppm/C; EIA_Code: E96; U/M: EA; AEC Category: Q200
TP1 TP2 = 5000: Test Point, TH, Miniature, Red; Manufacturer: Keystone; CompType: Test Point Loop; U/M: EA
TP3 = 5001: Test Point, Miniature, Black, TH; Manufacturer: Keystone; CompType: Test Point Loop; U/M: EA
U3 = TPS25740ARGER: USB Power Delivery (PD) Provider-Only and Type-C Downward Facing Port (DFP) Port Controller, RGE0024F; Alternate PartNumber: TPS25740ARGET; Manufacturer: Texas Instruments; SymbolCreator: Altium; CompType: IC; U/M: EA
U4 = UCC24636DBVR: SYNCRONOUS RECTIFIER CONTROLLER WITH LOW POWER STANDBY, DBV0006A; Alternate PartNumber: UCC24636DBVT; Manufacturer: Texas Instruments; SymbolCreator: a0411947; CompType: IC; U/M: EA
U5 = TL431AIDBZR: Adjustable Precision Shunt Regulator, 34 ppm / degC, 100 mA, -40 to 85 degC, 3-pin SOT-23 (DBZ), Green (RoHS & no Sb/Br); Manufacturer: Texas Instruments; Alternate PartNumber: Equivalent; Initial Accuracy @ 25/deg C(%): 1; Iout/Iz(Max)(mA): 100; Min Iz for Regulation(uA): 600; Rating: Catalog; SubFamily: Shunt Voltage Reference; Temp Coeff(Max)(ppm/ degree C): 92; Temp Coeff(Typ)(ppm/ degree C): 34; VO Adj(Max)(V): 36; VO Adj(Min)(V): 2.495

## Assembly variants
001: not fitted FID1 FID2 FID3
